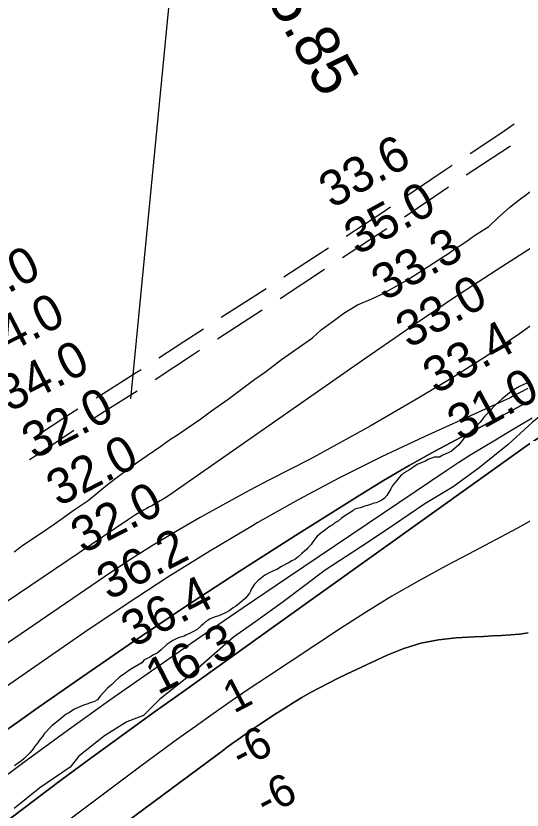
# Model space of a CAD drawing. Extents: x 3245246 to 3283090, y 806824 to 832173.
# Drawn here: x 3253367 to 3254318, y 818279 to 819772 of the extents above; entities that cross this region are included whole.
import ezdxf

# ---------------------------------------------------------------- set-up
doc = ezdxf.new("R2010")
doc.units = 0
for name, color, linetype in [('V-RIVR-EDGE', 7, 'Continuous'), ('V-RIVR-RANG', 7, 'Continuous'), ('V-RIVR-RANG-IDEN', 7, 'Continuous'), ('V-ROAD-CNTR', 7, 'Continuous'), ('V-SITE-VEGE', 7, 'Continuous'), ('V-TOPO-DPTH', 7, 'Continuous'), ('V-TOPO-MAJR', 7, 'Continuous'), ('V-TOPO-MINR', 7, 'Continuous'), ('V-TOPO-SHOR', 7, 'Continuous'), ('V-TOPO-WATR', 7, 'Continuous')]:
    doc.layers.add(name, color=color, linetype=linetype)

msp = doc.modelspace()

# ---------------------------------------------------------------- linework, layer by layer
at = {"layer": 'V-RIVR-EDGE'}
msp.add_lwpolyline([(3254463.6, 819090.9), (3254439.7, 819082.2), (3254410.1, 819061.4), (3254365.6, 819029.8), (3254337.8, 819008.1), (3254292, 818965.7), (3254237.6, 818921.9), (3254188.8, 818886.4), (3254135.7, 818854.3), (3254076.5, 818814.5), (3254027.3, 818781.1), (3253948, 818729.6), (3253868.8, 818670.3), (3253817.8, 818633), (3253776, 818604), (3253694.1, 818532.5), (3253637.5, 818487), (3253606.6, 818456.6), (3253575.3, 818444.5), (3253533.5, 818418.5), (3253485.1, 818380), (3253468.5, 818359.6), (3253411.5, 818320.6), (3253363.6, 818282)], dxfattribs=at)
at = {"layer": 'V-ROAD-CNTR'}
for p, q in [((3254097.4, 819394.1), (3254180.1, 819450.4)), ((3253980.4, 819317.2), (3254064.3, 819371.8)), ((3253863.3, 819240.6), (3253946.9, 819295.4)), ((3253745.6, 819164.8), (3253829.8, 819218.8))]:
    msp.add_line(p, q, dxfattribs=at)
for points in [[(3254220.5, 819513.1), (3254278.2, 819551.2), (3254303.7, 819568.5)], [(3254213.4, 819472.5), (3254294.9, 819526.3), (3254296.9, 819527.6)], [(3254104.3, 819435.1), (3254171.6, 819480.9), (3254187.1, 819491.1)], [(3253987.6, 819357.7), (3254056.2, 819402.4), (3254071.2, 819412.6)], [(3253870.4, 819281.2), (3253938.6, 819325.8), (3253954.1, 819335.9)], [(3253752.8, 819205.1), (3253817.6, 819246.6), (3253836.9, 819259.3)], [(3253635.3, 819129), (3253682.1, 819159.8), (3253719.1, 819183.5)], [(3253628.3, 819088.4), (3253698.4, 819134.6), (3253711.9, 819143.2)], [(3253517.3, 819053.7), (3253523.8, 819057.6), (3253592.9, 819101), (3253602, 819106.9)], [(3253509.8, 819013.8), (3253539.6, 819032.1), (3253594.7, 819066.7)], [(3253399.5, 818978.2), (3253462.5, 819019.9), (3253483.3, 819032.7)], [(3253392.4, 818937.6), (3253415.9, 818953.1), (3253475.8, 818992.7)]]:
    msp.add_lwpolyline(points, dxfattribs=at)
at = {"layer": 'V-SITE-VEGE'}
for p, q in [((3254312.8, 819426), (3254357, 819458.6)), ((3254295.3, 819412.1), (3254312.8, 819426)), ((3254272, 819391.1), (3254295.3, 819412.1)), ((3254255.8, 819376), (3254272, 819391.1)), ((3254229, 819358.5), (3254255.8, 819376)), ((3254212.7, 819346.9), (3254229, 819358.5)), ((3254189.4, 819331.8), (3254212.7, 819346.9)), ((3254131.2, 819293.4), (3254172, 819320.1)), ((3254172, 819320.1), (3254177.8, 819323.6)), ((3254177.8, 819323.6), (3254189.4, 819331.8)), ((3254099.8, 819273.6), (3254131.2, 819293.4)), ((3254055.6, 819249.2), (3254099.8, 819273.6)), ((3254035.8, 819239.9), (3254055.6, 819249.2)), ((3253983.4, 819213.1), (3254009, 819228.2)), ((3254009, 819228.2), (3254035.8, 819239.9)), ((3253968.3, 819201.5), (3253983.4, 819213.1)), ((3253940.4, 819181.7), (3253968.3, 819201.5)), ((3253924.1, 819166.6), (3253940.4, 819181.7)), ((3253865.9, 819125.9), (3253924.1, 819166.6)), ((3253835.6, 819102.6), (3253865.9, 819125.9)), ((3253815.9, 819088.6), (3253835.6, 819102.6)), ((3253785.6, 819066.5), (3253815.9, 819088.6)), ((3254331.4, 819082.9), (3254317.1, 819076.7)), ((3253765.8, 819051.4), (3253785.6, 819066.5)), ((3254300.8, 819068.2), (3254280.7, 819052.1)), ((3254305.6, 819070.6), (3254300.8, 819068.2)), ((3254313.2, 819074.8), (3254305.6, 819070.6)), ((3254317.1, 819076.7), (3254313.2, 819074.8)), ((3253734.4, 819029.3), (3253765.8, 819051.4)), ((3254280.7, 819052.1), (3254268.2, 819040.7)), ((3254264.9, 819037.3), (3254254.3, 819025.5)), ((3254268.2, 819040.7), (3254264.9, 819037.3)), ((3253714.6, 819014.2), (3253734.4, 819029.3)), ((3254254.3, 819025.5), (3254247.6, 819018.8)), ((3253686.7, 818995.6), (3253714.6, 819014.2)), ((3254239, 819007.4), (3254227.9, 818996)), ((3254242.3, 819011.7), (3254239, 819007.4)), ((3254244.2, 819015), (3254242.3, 819011.7)), ((3254247.6, 819018.8), (3254244.2, 819015)), ((3253670.4, 818983.9), (3253686.7, 818995.6)), ((3254221.2, 818989.8), (3254216.4, 818984.6)), ((3254227.9, 818996), (3254221.2, 818989.8)), ((3253639, 818963), (3253655.3, 818974.6)), ((3253655.3, 818974.6), (3253670.4, 818983.9)), ((3254210.2, 818978.9), (3254199.2, 818965.6)), ((3254214, 818982.7), (3254210.2, 818978.9)), ((3254216.4, 818984.6), (3254214, 818982.7)), ((3253613.4, 818945.5), (3253639, 818963)), ((3254199.2, 818965.6), (3254185.3, 818953.7)), ((3253593.6, 818931.6), (3253613.4, 818945.5)), ((3254169, 818945.7), (3254166.1, 818944.3)), ((3254179.5, 818950.4), (3254169, 818945.7)), ((3254185.3, 818953.7), (3254179.5, 818950.4)), ((3253562.2, 818908.3), (3253593.6, 818931.6)), ((3254128.8, 818931.6), (3254121.2, 818928.2)), ((3254137, 818934.9), (3254128.8, 818931.6)), ((3254141.3, 818937.7), (3254137, 818934.9)), ((3254153.2, 818941.9), (3254141.3, 818937.7)), ((3254159.9, 818942.4), (3254153.2, 818941.9)), ((3254163.3, 818942.4), (3254159.9, 818942.4)), ((3254166.1, 818944.3), (3254163.3, 818942.4)), ((3254101.1, 818915.5), (3254097.3, 818912.6)), ((3254106.8, 818918.3), (3254101.1, 818915.5)), ((3254121.2, 818928.2), (3254106.8, 818918.3)), ((3253538.9, 818890.9), (3253562.2, 818908.3)), ((3254089.6, 818906.9), (3254082.4, 818897.9)), ((3254092, 818908.8), (3254089.6, 818906.9)), ((3254094.4, 818911.2), (3254092, 818908.8)), ((3254097.3, 818912.6), (3254094.4, 818911.2)), ((3253502.8, 818860.6), (3253538.9, 818890.9)), ((3254073.8, 818887.4), (3254071.4, 818882.7)), ((3254075.7, 818890.3), (3254073.8, 818887.4)), ((3254082.4, 818897.9), (3254075.7, 818890.3)), ((3254064.1, 818869.8), (3254058.9, 818864.6)), ((3254066.1, 818873.1), (3254064.1, 818869.8)), ((3254069.9, 818879.3), (3254066.1, 818873.1)), ((3254071.4, 818882.7), (3254069.9, 818879.3)), ((3253476, 818843.2), (3253502.8, 818860.6)), ((3254039.7, 818855.6), (3254033.5, 818853.3)), ((3254044, 818856.5), (3254039.7, 818855.6)), ((3254049.8, 818858.9), (3254044, 818856.5)), ((3254054.6, 818861.3), (3254049.8, 818858.9)), ((3254058.9, 818864.6), (3254054.6, 818861.3)), ((3253438.8, 818816.4), (3253476, 818843.2)), ((3254000.1, 818841.5), (3253993.4, 818837.2)), ((3254002.5, 818843.8), (3254000.1, 818841.5)), ((3254005.8, 818845.3), (3254002.5, 818843.8)), ((3254013.9, 818847.1), (3254005.8, 818845.3)), ((3254022.5, 818850), (3254013.9, 818847.1)), ((3254027.8, 818851.4), (3254022.5, 818850)), ((3254033.5, 818853.3), (3254027.8, 818851.4)), ((3253978.5, 818827.3), (3253972.3, 818822)), ((3253987.1, 818832.9), (3253978.5, 818827.3)), ((3253993.4, 818837.2), (3253987.1, 818832.9)), ((3253413.2, 818798.9), (3253438.8, 818816.4)), ((3253957.5, 818812.6), (3253944.5, 818802.6)), ((3253963.2, 818815.9), (3253957.5, 818812.6)), ((3253966.5, 818818.7), (3253963.2, 818815.9)), ((3253972.3, 818822), (3253966.5, 818818.7)), ((3253379.5, 818776.8), (3253413.2, 818798.9)), ((3253935.9, 818796.4), (3253933, 818793.6)), ((3253939.7, 818799.3), (3253935.9, 818796.4)), ((3253944.5, 818802.6), (3253939.7, 818799.3)), ((3253923.9, 818781.2), (3253922, 818777.9)), ((3253926.8, 818785.5), (3253923.9, 818781.2)), ((3253930.6, 818790.7), (3253926.8, 818785.5)), ((3253933, 818793.6), (3253930.6, 818790.7)), ((3253363.2, 818764), (3253379.5, 818776.8)), ((3253913.8, 818769.3), (3253904.2, 818761.3)), ((3253915.7, 818771.7), (3253913.8, 818769.3)), ((3253922, 818777.9), (3253915.7, 818771.7)), ((3253897.5, 818755.1), (3253890.8, 818749.9)), ((3253904.2, 818761.3), (3253897.5, 818755.1)), ((3253864.5, 818736.2), (3253860.2, 818732.8)), ((3253880.3, 818744.2), (3253864.5, 818736.2)), ((3253885.1, 818747), (3253880.3, 818744.2)), ((3253890.8, 818749.9), (3253885.1, 818747)), ((3253845.4, 818725.7), (3253834.9, 818720.1)), ((3253848.7, 818727.2), (3253845.4, 818725.7)), ((3253852.1, 818729.1), (3253848.7, 818727.2)), ((3253856.9, 818730.9), (3253852.1, 818729.1)), ((3253860.2, 818732.8), (3253856.9, 818730.9)), ((3253821.4, 818709.6), (3253815.2, 818703.5)), ((3253824.8, 818712), (3253821.4, 818709.6)), ((3253828.2, 818715.3), (3253824.8, 818712)), ((3253834.9, 818720.1), (3253828.2, 818715.3)), ((3253808, 818690.6), (3253805.6, 818686.3)), ((3253809.4, 818694.4), (3253808, 818690.6)), ((3253815.2, 818703.5), (3253809.4, 818694.4)), ((3253797.4, 818676.8), (3253785.5, 818666.4)), ((3253801.3, 818681.1), (3253797.4, 818676.8)), ((3253805.6, 818686.3), (3253801.3, 818681.1)), ((3253779.2, 818661.6), (3253774.9, 818658.8)), ((3253785.5, 818666.4), (3253779.2, 818661.6)), ((3253761, 818649.3), (3253748.1, 818644.1)), ((3253767.7, 818653.6), (3253761, 818649.3)), ((3253774.9, 818658.8), (3253767.7, 818653.6)), ((3253723.3, 818632.8), (3253718.5, 818628.5)), ((3253727.6, 818635.1), (3253723.3, 818632.8)), ((3253730.4, 818637.5), (3253727.6, 818635.1)), ((3253736.2, 818640.3), (3253730.4, 818637.5)), ((3253741, 818641.8), (3253736.2, 818640.3)), ((3253748.1, 818644.1), (3253741, 818641.8)), ((3253707.4, 818618.5), (3253700.3, 818614.3)), ((3253715.1, 818625.2), (3253707.4, 818618.5)), ((3253718.5, 818628.5), (3253715.1, 818625.2)), ((3253673.5, 818603.4), (3253666.8, 818600.1)), ((3253678.7, 818604.3), (3253673.5, 818603.4)), ((3253683, 818605.8), (3253678.7, 818604.3)), ((3253686.4, 818607.6), (3253683, 818605.8)), ((3253695.5, 818611.9), (3253686.4, 818607.6)), ((3253700.3, 818614.3), (3253695.5, 818611.9)), ((3253650.5, 818590.2), (3253640, 818580.2)), ((3253657.7, 818594.9), (3253650.5, 818590.2)), ((3253661.5, 818597.7), (3253657.7, 818594.9)), ((3253666.8, 818600.1), (3253661.5, 818597.7)), ((3253632.3, 818574), (3253624.2, 818569.8)), ((3253636.1, 818576.9), (3253632.3, 818574)), ((3253640, 818580.2), (3253636.1, 818576.9)), ((3253607.9, 818561.2), (3253603.6, 818555.5)), ((3253610.8, 818562.2), (3253607.9, 818561.2)), ((3253613.7, 818563.6), (3253610.8, 818562.2)), ((3253621.8, 818567.9), (3253613.7, 818563.6)), ((3253624.2, 818569.8), (3253621.8, 818567.9)), ((3253581.1, 818542.3), (3253568.7, 818533.7)), ((3253603.6, 818555.5), (3253581.1, 818542.3)), ((3253562, 818529), (3253551.4, 818519)), ((3253568.7, 818533.7), (3253562, 818529)), ((3253543.3, 818511.9), (3253538.5, 818507.6)), ((3253546.1, 818514.3), (3253543.3, 818511.9)), ((3253551.4, 818519), (3253546.1, 818514.3)), ((3253538.5, 818507.6), (3253525, 818492.9)), ((3253513.1, 818482), (3253506.4, 818480.6)), ((3253519.8, 818486.2), (3253513.1, 818482)), ((3253522.6, 818490), (3253519.8, 818486.2)), ((3253525, 818492.9), (3253522.6, 818490)), ((3253476.7, 818468.8), (3253466.2, 818461.7)), ((3253489.2, 818474), (3253476.7, 818468.8)), ((3253494, 818476.3), (3253489.2, 818474)), ((3253502.1, 818478.7), (3253494, 818476.3)), ((3253506.4, 818480.6), (3253502.1, 818478.7)), ((3253461.4, 818458.8), (3253449, 818448.9)), ((3253466.2, 818461.7), (3253461.4, 818458.8)), ((3253435.1, 818437.5), (3253429.8, 818432.7)), ((3253449, 818448.9), (3253435.1, 818437.5)), ((3253419.7, 818422.3), (3253416.4, 818417)), ((3253423.6, 818426.1), (3253419.7, 818422.3)), ((3253429.8, 818432.7), (3253423.6, 818426.1)), ((3253410.6, 818409.9), (3253408.2, 818406.6)), ((3253416.4, 818417), (3253410.6, 818409.9)), ((3253399.1, 818393.7), (3253393.3, 818387.1)), ((3253402.4, 818399), (3253399.1, 818393.7)), ((3253406.8, 818403.7), (3253402.4, 818399)), ((3253408.2, 818406.6), (3253406.8, 818403.7)), ((3253393.3, 818387.1), (3253381.8, 818375.2)), ((3253368.9, 818365.7), (3253364.1, 818361.9)), ((3253377, 818371.4), (3253368.9, 818365.7)), ((3253381.8, 818375.2), (3253377, 818371.4))]:
    msp.add_line(p, q, dxfattribs=at)
at = {"layer": 'V-TOPO-DPTH'}
for points in [[(3253112.8, 818078.8), (3253396.3, 818293.4), (3253453, 818336), (3253510, 818378.2), (3253567.3, 818419.9), (3253624.8, 818461.4), (3253682.5, 818502.6), (3253740.2, 818543.8), (3253797.9, 818585), (3253855.6, 818626.3), (3254328.5, 818964.4), (3254647.9, 819174.3), (3254703.8, 819213.1), (3254758.2, 819253.8), (3254810.4, 819297.3), (3254861.2, 819342.7), (3254960.5, 819436.2), (3255609.1, 819769.1), (3255713, 819823.5)], [(3255713, 819823.5), (3255609.1, 819769.1), (3254960.5, 819436.2), (3254861.2, 819342.7), (3254810.4, 819297.3), (3254758.2, 819253.8), (3254703.8, 819213.1), (3254647.9, 819174.3), (3254328.5, 818964.4), (3253855.6, 818626.3), (3253797.9, 818585), (3253740.2, 818543.8), (3253682.5, 818502.6), (3253624.8, 818461.4), (3253567.3, 818419.9), (3253510, 818378.2), (3253453, 818336), (3253396.3, 818293.4), (3253112.8, 818078.8)], [(3253327.3, 818414.2), (3253404.2, 818468.8), (3253474.2, 818517.6), (3253577.5, 818588.7), (3253681.5, 818658.8), (3253786.5, 818727.3), (3253892.2, 818794.9), (3254010, 818869), (3254057.6, 818898.1), (3254105.7, 818926.4), (3254154.5, 818953.5), (3254203.8, 818979.9), (3254276.9, 819017.7), (3254289.9, 819024.6), (3254302.8, 819031.6), (3254315.6, 819038.7), (3254328.4, 819046)], [(3253074.7, 817886.5), (3253744.9, 818382.9), (3253754.3, 818389.8), (3253763.7, 818396.8), (3253773.2, 818403.7), (3253782.6, 818410.5), (3253792.2, 818417.3), (3253801.8, 818424.1), (3253811.4, 818430.7), (3253821.1, 818437.2), (3253856.2, 818460.4), (3253872, 818470.6), (3253888.1, 818480.6), (3253904.3, 818490.3), (3253920.7, 818499.7), (3253937.3, 818508.7), (3253954.1, 818517.5), (3253971, 818525.9), (3253988, 818534.1), (3254064.8, 818569.9), (3254096.2, 818582.4), (3254128.1, 818592.3), (3254161, 818598.6), (3254194.5, 818602.4), (3254228.6, 818604.3), (3254245.5, 818605.2), (3254262.5, 818606.2), (3254279.5, 818607.1), (3254296.4, 818608), (3254313.3, 818609.6), (3254329.9, 818612.1)], [(3254329.9, 818612.1), (3254313.3, 818609.6), (3254296.4, 818608), (3254279.5, 818607.1), (3254262.5, 818606.2), (3254245.5, 818605.2), (3254228.6, 818604.3), (3254194.5, 818602.4), (3254161, 818598.6), (3254128.1, 818592.3), (3254096.2, 818582.4), (3254064.8, 818569.9), (3253988, 818534.1), (3253971, 818525.9), (3253954.1, 818517.5), (3253937.3, 818508.7), (3253920.7, 818499.7), (3253904.3, 818490.3), (3253888.1, 818480.6), (3253872, 818470.6), (3253856.2, 818460.4), (3253821.1, 818437.2), (3253811.4, 818430.7), (3253801.8, 818424.1), (3253792.2, 818417.3), (3253782.6, 818410.5), (3253773.2, 818403.7), (3253763.7, 818396.8), (3253754.3, 818389.8), (3253744.9, 818382.9), (3253074.7, 817886.5)]]:
    msp.add_lwpolyline(points, dxfattribs=at)
at = {"layer": 'V-TOPO-MAJR'}
msp.add_lwpolyline([(3254369.1, 819357.1), (3254279.9, 819300), (3254191.2, 819242), (3254103.4, 819182.8), (3254016.1, 819122.8), (3253653.6, 818869.7), (3253648.5, 818866.3), (3253643.4, 818863), (3253638.1, 818859.8), (3253632.8, 818856.8), (3253627.4, 818853.9), (3253622.1, 818850.9), (3253616.7, 818848), (3253611.3, 818845), (3253606.6, 818842.4), (3253599, 818838), (3253591.4, 818833.5), (3253584, 818828.8), (3253576.6, 818823.9), (3252848.9, 818332.7)], dxfattribs=at)
at = {"layer": 'V-TOPO-MINR'}
for points in [[(3254374.1, 819218), (3254313.3, 819174.2), (3254251.5, 819132), (3254188.3, 819091.9), (3254124.1, 819053.4), (3254032.6, 819000.6), (3253995.3, 818979.5), (3253957.7, 818958.8), (3253919.8, 818938.7), (3253881.7, 818919.1), (3253843.5, 818899.5), (3253805.5, 818879.5), (3253767.8, 818859.1), (3253730.2, 818838.4), (3253712.8, 818828.6), (3253667, 818802.1), (3253621.7, 818774.9), (3253577.2, 818746.4), (3253533.1, 818717.2), (3253036.7, 818378.1)], [(3254328.8, 819071.1), (3254300.2, 819055.9), (3254297.4, 819054.4), (3254294.7, 819053), (3254291.9, 819051.7), (3254289, 819050.4), (3254133.9, 818980.1), (3254054.1, 818942.5), (3253975.2, 818903.3), (3253897.4, 818861.8), (3253820.5, 818818.6), (3253811.6, 818813.3), (3253731.4, 818765.4), (3253652, 818716.3), (3253573.7, 818665.3), (3253496.3, 818613.1), (3253221.7, 818423.4)], [(3254328.4, 819046), (3254315.6, 819038.7), (3254302.8, 819031.6), (3254289.9, 819024.6), (3254276.9, 819017.7), (3254203.8, 818979.9), (3254154.5, 818953.5), (3254105.7, 818926.4), (3254057.6, 818898.1), (3254010, 818869), (3253892.2, 818794.9), (3253786.5, 818727.3), (3253681.5, 818658.8), (3253577.5, 818588.7), (3253474.2, 818517.6), (3253404.2, 818468.8), (3253327.3, 818414.2)], [(3254337.2, 819015.4), (3254314.2, 819001.5), (3254291.1, 818987.8), (3254268, 818974.2), (3254244.9, 818960.5), (3254222, 818946.5), (3254199.4, 818932), (3254177, 818917.2), (3253877.3, 818715.5), (3253793.8, 818658.9), (3253710.5, 818601.9), (3253627.7, 818544.3), (3253545.1, 818486.4), (3253463, 818427.7), (3253381.4, 818368.4), (3253300.5, 818308.1)], [(3254340, 818825.4), (3254309.5, 818808.7), (3254278.9, 818792.2), (3254248.3, 818775.9), (3254217.5, 818759.6), (3254175.7, 818737.7), (3254124.4, 818709.8), (3254073.7, 818680.9), (3254024, 818650.5), (3253974.8, 818619), (3253839.6, 818529.5), (3253805.4, 818506.5), (3253771.4, 818483.4), (3253737.6, 818459.8), (3253704.1, 818436), (3253670.7, 818411.9), (3253637.4, 818387.6), (3253604.3, 818363.2), (3253571.3, 818338.6), (3253095.4, 817982.3)], [(3254329.9, 818612.1), (3254313.3, 818609.6), (3254296.4, 818608), (3254279.5, 818607.1), (3254262.5, 818606.2), (3254245.5, 818605.2), (3254228.6, 818604.3), (3254194.5, 818602.4), (3254161, 818598.6), (3254128.1, 818592.3), (3254096.2, 818582.4), (3254064.8, 818569.9), (3253988, 818534.1), (3253971, 818525.9), (3253954.1, 818517.5), (3253937.3, 818508.7), (3253920.7, 818499.7), (3253904.3, 818490.3), (3253888.1, 818480.6), (3253872, 818470.6), (3253856.2, 818460.4), (3253821.1, 818437.2), (3253811.4, 818430.7), (3253801.8, 818424.1), (3253792.2, 818417.3), (3253782.6, 818410.5), (3253773.2, 818403.7), (3253763.7, 818396.8), (3253754.3, 818389.8), (3253744.9, 818382.9), (3253074.7, 817886.5)]]:
    msp.add_lwpolyline(points, dxfattribs=at)
at = {"layer": 'V-TOPO-SHOR'}
msp.add_line((3253775.5, 821035.4), (3253582, 819051.9), dxfattribs=at)
at = {"layer": 'V-TOPO-WATR'}
msp.add_lwpolyline([(3255713, 819823.5), (3255609.1, 819769.1), (3254960.5, 819436.2), (3254861.2, 819342.7), (3254810.4, 819297.3), (3254758.2, 819253.8), (3254703.8, 819213.1), (3254647.9, 819174.3), (3254328.5, 818964.4), (3253855.6, 818626.3), (3253797.9, 818585), (3253740.2, 818543.8), (3253682.5, 818502.6), (3253624.8, 818461.4), (3253567.3, 818419.9), (3253510, 818378.2), (3253453, 818336), (3253396.3, 818293.4), (3253112.8, 818078.8)], dxfattribs=at)

# ---------------------------------------------------------------- texts
at = {"layer": 'V-RIVR-RANG'}
for s, height, rotation, p in [('33.6', 67, 28.8383, (3253960.8, 819408.6)), ('35.0', 67, 28.8383, (3254008.3, 819320.7)), ('33.3', 67, 28.8383, (3254059.3, 819234.6)), ('34.0', 67, 27.2583, (3253262.6, 819203.5)), ('33.0', 67, 28.8383, (3254105.2, 819145.7)), ('34.0', 67, 27.2583, (3253308.6, 819114.7)), ('33.4', 67, 28.8383, (3254156.2, 819059.6)), ('34.0', 67, 27.2583, (3253354.6, 819026)), ('31.0', 67, 28.8383, (3254202.1, 818970.7)), ('32.0', 67, 27.2583, (3253400.6, 818937.2)), ('32.0', 67, 27.2583, (3253446.7, 818848.4)), ('32.0', 67, 27.2583, (3253492.7, 818759.6)), ('36.2', 67, 27.2583, (3253541.3, 818672.2)), ('36.4', 67, 27.2583, (3253587.3, 818583.4)), ('16.3', 67, 27.2583, (3253633.3, 818494.6)), ('1', 60, 27.555, (3253776.3, 818459.7)), ('-6', 60, 27.555, (3253790.3, 818354.2)), ('-6', 60, 27.555, (3253836.3, 818265.4))]:
    msp.add_text(s, height=height, rotation=rotation, dxfattribs=at).set_placement(p)
at = {"layer": 'V-RIVR-RANG-IDEN'}
msp.add_text('R-265.85', height=83, rotation=298.9809, dxfattribs=at).set_placement((3253721.5, 820013.7))

doc.saveas('drawing.dxf')
